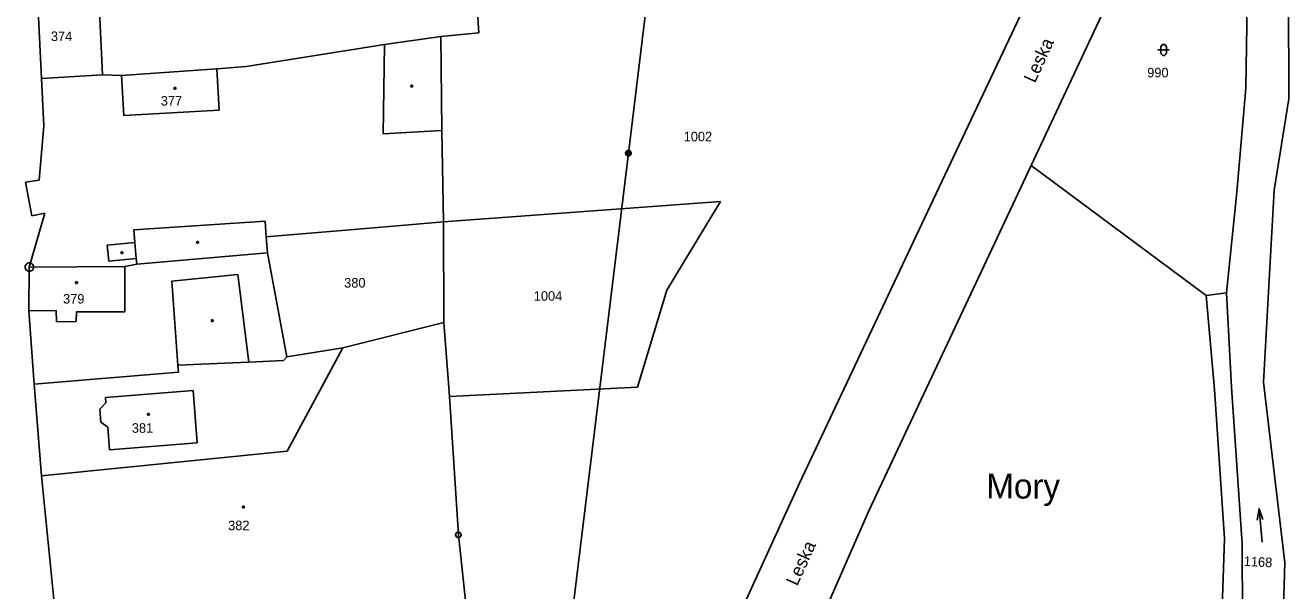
# Model space of a CAD drawing. Extents: x -812394 to -807601, y -1013098 to -1009266.
# Drawn here: x -810995.8 to -810771.4, y -1011512.4 to -1011411.9 of the extents above; entities that cross this region are included whole.
import ezdxf

# ---------------------------------------------------------------- set-up
doc = ezdxf.new("R2010")
doc.units = 0
for name, color, linetype in [('KN_HRANICE', 7, 'Continuous'), ('KN_KULTURY', 7, 'Continuous'), ('KN_MEZNIKY', 7, 'Continuous'), ('KN_PARCELY', 7, 'Continuous'), ('KN_SLUCKY', 7, 'Continuous'), ('KN_VEDENI', 7, 'Continuous')]:
    doc.layers.add(name, color=color, linetype=linetype)

# ---------------------------------------------------------------- blocks, each defined once
blk = doc.blocks.new('101')
blk.add_line((-0.05, 0), (0.05, 0))
blk.add_lwpolyline([(0.19, 0.72), (0.53, 0.53), (0.72, 0.19), (0.72, -0.2), (0.53, -0.54), (0.19, -0.73), (-0.2, -0.73), (-0.54, -0.54), (-0.73, -0.2), (-0.73, 0.19), (-0.54, 0.53), (-0.2, 0.72), (0.19, 0.72)])
blk = doc.blocks.new('316')
for points in [[(-1, 1), (0.27, 1), (1, 1)], [(-0.5, 1.5), (-0.4, 1.79), (-0.15, 1.97), (0.16, 1.97), (0.41, 1.79), (0.51, 1.5), (0.51, 0.5), (0.41, 0.21), (0.16, 0.03), (-0.15, 0.03), (-0.4, 0.21), (-0.5, 0.5), (-0.5, 1.5)]]:
    blk.add_lwpolyline(points)
blk = doc.blocks.new('NAHRADNI_SYMBOL')
blk.add_lwpolyline([(0.09, 0.15), (0.18, 0), (0.09, -0.15), (-0.09, -0.15), (-0.18, 0), (-0.09, 0.15), (0.09, 0.15)])
blk = doc.blocks.new('802')
blk.add_line((-3, 0), (3, 0))
blk.add_lwpolyline([(1, 0.5), (3, 0), (1, -0.5)])
blk = doc.blocks.new('402')
blk.add_lwpolyline([(0.09, 0.15), (0.18, 0), (0.09, -0.15), (-0.09, -0.15), (-0.18, 0), (-0.09, 0.15), (0.09, 0.15)])
blk = doc.blocks.new('105')
blk.add_line((-0.12, 0), (0.12, 0))
blk.add_lwpolyline([(0.15, 0.48), (0.4, 0.3), (0.5, 0.01), (0.4, -0.28), (0.15, -0.46), (-0.16, -0.46), (-0.41, -0.28), (-0.51, 0.01), (-0.41, 0.3), (-0.16, 0.48), (0.15, 0.48)])
blk = doc.blocks.new('601')
blk.add_lwpolyline([(-0.15, 0.48), (0.16, 0.48), (0.41, 0.3), (0.51, 0.01), (0.41, -0.28), (0.16, -0.46), (-0.15, -0.46), (-0.4, -0.28), (-0.5, 0.01), (-0.4, 0.3), (-0.15, 0.48), (-0.12, 0.44), (0.12, 0.44), (0.28, 0.36), (-0.28, 0.36), (-0.36, 0.28), (0.36, 0.28), (0.36, 0.2), (-0.36, 0.2), (-0.4, 0.12), (0.4, 0.12), (0.44, 0.04), (-0.44, 0.04), (-0.44, -0.04), (0.44, -0.04), (0.41, -0.12), (-0.4, -0.12), (-0.39, -0.2), (0.42, -0.2), (0.37, -0.28), (-0.35, -0.28), (-0.27, -0.36), (0.29, -0.36), (0.18, -0.44), (-0.16, -0.44)])

msp = doc.modelspace()

# ---------------------------------------------------------------- linework, layer by layer
at = {"layer": 'KN_HRANICE'}
for p, q in [((-810835.54, -1011445.05), (-810807.37, -1011385.45)), ((-810915.25, -1011413.2), (-810916.55, -1011393.72)), ((-810771.46, -1011394.94), (-810771.36, -1011424.92)), ((-810992.93, -1011421.31), (-810993.69, -1011405.27)), ((-810921.99, -1011413.85), (-810931.99, -1011415.27)), ((-810921.99, -1011413.85), (-810915.25, -1011413.2)), ((-810921.99, -1011413.85), (-810921.79, -1011430.55)), ((-810956.57, -1011419.22), (-810931.99, -1011415.27)), ((-810982.08, -1011420.69), (-810992.93, -1011421.31)), ((-810982.08, -1011420.69), (-810978.74, -1011420.81)), ((-810978.74, -1011420.81), (-810961.79, -1011419.59)), ((-810961.79, -1011419.59), (-810956.57, -1011419.22)), ((-810992.53, -1011429.75), (-810992.93, -1011421.31)), ((-810771.36, -1011424.92), (-810773.93, -1011441.2)), ((-810993.32, -1011439.39), (-810992.53, -1011429.75)), ((-810921.79, -1011430.55), (-810921.54, -1011446.8)), ((-810786.05, -1011459.9), (-810817.11, -1011436.78)), ((-810995.78, -1011439.78), (-810993.32, -1011439.39)), ((-810994.65, -1011445.73), (-810995.78, -1011439.78)), ((-810773.93, -1011441.2), (-810775.87, -1011475.3)), ((-810872.3, -1011443.19), (-810921.54, -1011446.8)), ((-810881.86, -1011458.96), (-810872.3, -1011443.19)), ((-810995.12, -1011454.86), (-810992.33, -1011445.29)), ((-810992.33, -1011445.29), (-810994.65, -1011445.73)), ((-810858.26, -1011493.31), (-810835.54, -1011445.05)), ((-810931.8, -1011447.68), (-810952.99, -1011449.5)), ((-810921.54, -1011446.8), (-810931.8, -1011447.68)), ((-810921.46, -1011464.71), (-810921.54, -1011446.8)), ((-810952.99, -1011449.5), (-810952.79, -1011452.34)), ((-810952.79, -1011452.34), (-810976.02, -1011454.34)), ((-810952.79, -1011452.34), (-810949.37, -1011470.8)), ((-810995.12, -1011454.86), (-810978.15, -1011454.73)), ((-810978.15, -1011454.73), (-810976.02, -1011454.34)), ((-810995.17, -1011462.65), (-810995.12, -1011454.86)), ((-810887.03, -1011476.21), (-810881.86, -1011458.96)), ((-810786.05, -1011459.9), (-810782.41, -1011459.43)), ((-810784.57, -1011476.64), (-810786.05, -1011459.9)), ((-810994.25, -1011475.67), (-810995.17, -1011462.65)), ((-810939.39, -1011469.21), (-810921.46, -1011464.71)), ((-810920.62, -1011475.48), (-810921.46, -1011464.71)), ((-810949.37, -1011470.8), (-810939.39, -1011469.21)), ((-810949.29, -1011487.58), (-810939.39, -1011469.21)), ((-810968.68, -1011472.29), (-810956.08, -1011471.75)), ((-810968.61, -1011473.55), (-810968.68, -1011472.29)), ((-810956.08, -1011471.75), (-810949.91, -1011471.49)), ((-810949.91, -1011471.49), (-810949.37, -1011470.8)), ((-810994.25, -1011475.67), (-810968.61, -1011473.55)), ((-810992.93, -1011491.98), (-810994.25, -1011475.67)), ((-810920.46, -1011477.89), (-810920.62, -1011475.48)), ((-810920.46, -1011477.89), (-810887.03, -1011476.21)), ((-810782.75, -1011503.15), (-810784.57, -1011476.64)), ((-810918.87, -1011502.5), (-810920.46, -1011477.89)), ((-810992.93, -1011491.98), (-810949.29, -1011487.58)), ((-810990.65, -1011514.5), (-810992.93, -1011491.98)), ((-810878.11, -1011536.55), (-810858.26, -1011493.31)), ((-810916.42, -1011525.41), (-810918.87, -1011502.5)), ((-810783.24, -1011517.2), (-810782.75, -1011503.15))]:
    msp.add_line(p, q, dxfattribs=at)
for points in [[(-810817.11, -1011436.78), (-810799.71, -1011399.57), (-810781.64, -1011360.53), (-810777.84, -1011351.43)], [(-810777.84, -1011351.43), (-810779.49, -1011369.6), (-810778.58, -1011396.9), (-810779, -1011423.07), (-810780.56, -1011441.53), (-810782.41, -1011459.43)], [(-810887.79, -1011588.2), (-810877.76, -1011568.21), (-810866.95, -1011544.7), (-810857.48, -1011524.61), (-810845.94, -1011498.21), (-810817.11, -1011436.78)], [(-810782.41, -1011459.43), (-810781.54, -1011476.23), (-810779.65, -1011504.07), (-810779.6, -1011517.24), (-810782.3, -1011526.63)], [(-810786.65, -1011550.55), (-810780.03, -1011540.57), (-810775.59, -1011530.62), (-810772.3, -1011515.42), (-810772.06, -1011507.46), (-810775.87, -1011475.3)]]:
    msp.add_lwpolyline(points, dxfattribs=at)
at = {"layer": 'KN_SLUCKY'}
for p, q in [((-810982.89, -1011404.38), (-810982.08, -1011420.69)), ((-810932.22, -1011431.17), (-810931.99, -1011415.27)), ((-810978.33, -1011427.93), (-810978.74, -1011420.81)), ((-810961.36, -1011426.93), (-810961.79, -1011419.59)), ((-810978.33, -1011427.93), (-810961.36, -1011426.93)), ((-810921.79, -1011430.55), (-810932.22, -1011431.17)), ((-810953.18, -1011446.7), (-810976.54, -1011448.25)), ((-810953.18, -1011446.7), (-810952.99, -1011449.5)), ((-810976.35, -1011450.49), (-810976.54, -1011448.25)), ((-810981.24, -1011450.96), (-810976.35, -1011450.49)), ((-810980.96, -1011453.81), (-810981.24, -1011450.96)), ((-810976.11, -1011453.34), (-810976.35, -1011450.49)), ((-810976.11, -1011453.34), (-810980.96, -1011453.81)), ((-810978.15, -1011454.73), (-810978.15, -1011462.8)), ((-810976.02, -1011454.34), (-810976.11, -1011453.34)), ((-810969.76, -1011457.38), (-810958.06, -1011456.19)), ((-810958.06, -1011456.19), (-810956.08, -1011471.75)), ((-810968.68, -1011472.29), (-810969.76, -1011457.38)), ((-810990.32, -1011462.59), (-810995.17, -1011462.65)), ((-810990.26, -1011464.62), (-810990.32, -1011462.59)), ((-810986.71, -1011462.8), (-810986.76, -1011464.51)), ((-810978.15, -1011462.8), (-810986.71, -1011462.8)), ((-810986.76, -1011464.51), (-810990.26, -1011464.62)), ((-810965.99, -1011476.83), (-810981.58, -1011478.05)), ((-810965.25, -1011486.14), (-810965.99, -1011476.83)), ((-810981.51, -1011479.03), (-810982.58, -1011480.15)), ((-810981.58, -1011478.05), (-810981.51, -1011479.03)), ((-810982.58, -1011480.15), (-810982.4, -1011482.42)), ((-810982.4, -1011482.42), (-810981.17, -1011483.32)), ((-810981.17, -1011483.32), (-810980.85, -1011487.37)), ((-810980.85, -1011487.37), (-810965.25, -1011486.14))]:
    msp.add_line(p, q, dxfattribs=at)
at = {"layer": 'KN_VEDENI'}
msp.add_lwpolyline([(-810881.42, -1011374.93), (-810888.67, -1011434.63), (-810899.49, -1011523.39), (-810905.13, -1011563.44)], dxfattribs=at)

# ---------------------------------------------------------------- block references
at = {"layer": 'KN_KULTURY'}
for name, p in [('316', (-810793.59, -1011417.24)), ('402', (-810969.23, -1011423.06)), ('402', (-810927.16, -1011422.66)), ('402', (-810978.65, -1011452.29)), ('402', (-810965.21, -1011450.47)), ('402', (-810986.71, -1011457.63)), ('402', (-810962.59, -1011464.41)), ('402', (-810973.92, -1011481.04)), ('NAHRADNI_SYMBOL', (-810957.06, -1011497.52))]:
    msp.add_blockref(name, p, dxfattribs=at)
at = {"layer": 'KN_KULTURY', "rotation": 95.34017700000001}
msp.add_blockref('802', (-810776.35, -1011500.82), dxfattribs=at)
at = {"layer": 'KN_MEZNIKY'}
for name, p in [('101', (-810995.08, -1011454.85)), ('105', (-810918.87, -1011502.5))]:
    msp.add_blockref(name, p, dxfattribs=at)
at = {"layer": 'KN_VEDENI'}
msp.add_blockref('601', (-810888.67, -1011434.63), dxfattribs=at)

# ---------------------------------------------------------------- texts
at = {"layer": 'KN_PARCELY'}
for s, p in [('374', (-810991.26, -1011414.67)), ('990', (-810796.5, -1011421.13)), ('377', (-810971.74, -1011426.14)), ('1002', (-810878.85, -1011432.5)), ('380', (-810939.16, -1011458.51)), ('1004', (-810905.47, -1011460.85)), ('379', (-810989.1, -1011461.35)), ('381', (-810976.88, -1011484.33)), ('382', (-810959.77, -1011501.66))]:
    msp.add_text(s, height=1.7, dxfattribs=at).set_placement(p)
for s, height, rotation, p in [('Leska', 2.3, 65.317, (-810816.45, -1011422.26)), ('Mory', 4.4, 359.817, (-810825.08, -1011496)), ('Leska', 2.3, 65.546, (-810858.68, -1011511.69)), ('1168', 1.7, 356.953, (-810779.38, -1011507.99))]:
    msp.add_text(s, height=height, rotation=rotation, dxfattribs=at).set_placement(p)

doc.saveas('drawing.dxf')
